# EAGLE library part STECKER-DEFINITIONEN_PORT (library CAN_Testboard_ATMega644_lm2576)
Datenportstecker Kompatibel zu den Steckern des STK500
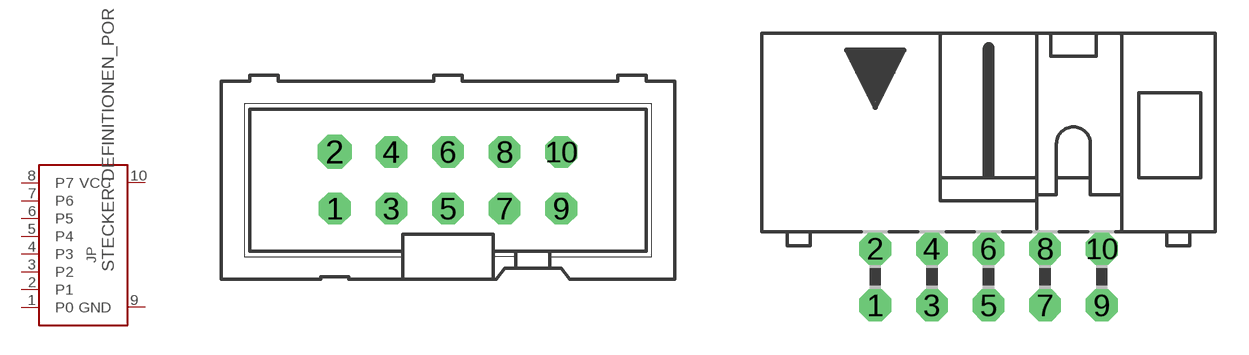
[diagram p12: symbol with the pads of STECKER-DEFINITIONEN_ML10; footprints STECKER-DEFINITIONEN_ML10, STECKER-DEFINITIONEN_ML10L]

Designator prefix JP

## STECKER-DEFINITIONEN_PORT  [STECKER-DEFINITIONEN_ML10]
1  P0
2  P1
3  P2
4  P3
5  P4
6  P5
7  P6
8  P7
9  GND  pwr
10  VCC  pwr

## STECKER-DEFINITIONEN_PORTL  [STECKER-DEFINITIONEN_ML10L]
Pads as for STECKER-DEFINITIONEN_ML10

## STECKER-DEFINITIONEN_PORTM  [STECKER-DEFINITIONEN_3M_10L]
Pads as for STECKER-DEFINITIONEN_ML10

## STECKER-DEFINITIONEN_PORTS  [STECKER-DEFINITIONEN_2X05]
Pads as for STECKER-DEFINITIONEN_ML10

## STECKER-DEFINITIONEN_PORTSV  [STECKER-DEFINITIONEN_2X05/90]
Pads as for STECKER-DEFINITIONEN_ML10

## Footprint STECKER-DEFINITIONEN_ML10 (pad centres in mm)
HARTING
drill 0.914 pad 1.422 octagon: 1 -5.08,-1.27; 3 -2.54,-1.27; 4 -2.54,1.27
drill 1.016 pad 1.422 octagon: 2 -5.08,1.27
drill 0.914 octagon: 5 0,-1.27; 6 0,1.27; 7 2.54,-1.27; 8 2.54,1.27; 9 5.08,-1.27; 10 5.08,1.27

## Footprint STECKER-DEFINITIONEN_ML10L (pad centres in mm)
HARTING
drill 0.914 octagon: 1 -5.08,-1.27; 2 -5.08,1.27; 3 -2.54,-1.27; 4 -2.54,1.27; 5 0,-1.27; 6 0,1.27; 7 2.54,-1.27; 8 2.54,1.27; 9 5.08,-1.27; 10 5.08,1.27

## Footprint STECKER-DEFINITIONEN_3M_10L (pad centres in mm)
3M
drill 1.016 octagon: 1 -5.08,-1.27; 2 -5.08,1.27; 3 -2.54,-1.27; 4 -2.54,1.27; 5 0,-1.27; 6 0,1.27; 7 2.54,-1.27; 8 2.54,1.27; 9 5.08,-1.27; 10 5.08,1.27
hole 2.54 at -10.998,0.533
hole 2.54 at 10.998,0.533

## Footprint STECKER-DEFINITIONEN_2X05 (pad centres in mm)
PIN HEADER
drill 1.016 octagon: 1 -5.08,-1.27; 2 -5.08,1.27; 3 -2.54,-1.27; 4 -2.54,1.27; 5 0,-1.27; 6 0,1.27; 7 2.54,-1.27; 8 2.54,1.27; 9 5.08,-1.27; 10 5.08,1.27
